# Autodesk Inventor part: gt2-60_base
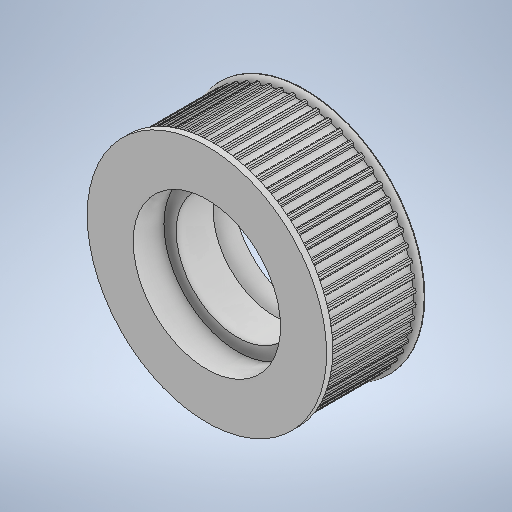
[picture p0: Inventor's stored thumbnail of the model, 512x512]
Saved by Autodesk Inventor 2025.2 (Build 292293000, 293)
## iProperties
Created: 2025-06
Part Number: gt2-60_base
Material: Generico
Document SubType Name: Modeling
Designer: Ryzen5700u
Density: 1 g/cm^3
Appearance: Default
Author: Ryzen5700u
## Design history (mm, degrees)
sketch "Schizzo1"
  geometry: C1 r 4.963 at (0, 0); A1 r 18.592 centre (0, 0) between (-0.5, -18.585) and (0.5, -18.585); A2 r 0.65 centre (0, -19) between (0.628, -18.833) and (0.5, -18.585); A3 r 0.2 centre (0.822, -18.782) between (0.628, -18.833) and (0.83, -18.982); A4 r 19 centre (0, 0) between (0.83, -18.982) and (1.158, -18.965); A5 r 0.2 centre (1.146, -18.765) between (1.158, -18.965) and (1.344, -18.796); A6 r 0.65 centre (1.986, -18.896) between (1.445, -18.536) and (1.344, -18.796); A7 r 18.592 centre (0, 0) between (1.445, -18.536) and (2.44, -18.431); A8 r 0.65 centre (1.986, -18.896) between (2.593, -18.664) and (2.44, -18.431); A9 r 0.2 centre (2.78, -18.593) between (2.593, -18.664) and (2.81, -18.791); A10 r 19 centre (0, 0) between (2.81, -18.791) and (3.134, -18.74); A11 r 0.2 centre (3.101, -18.542) between (3.134, -18.74) and (3.301, -18.552); A12 r 0.65 centre (3.95, -18.585) between (3.375, -18.283) and (3.301, -18.552); A13 r 18.592 centre (0, 0) between (3.375, -18.283) and (4.354, -18.075); A14 r 0.65 centre (3.95, -18.585) between (4.53, -18.291) and (4.354, -18.075); A15 r 0.2 centre (4.709, -18.201) between (4.53, -18.291) and (4.759, -18.394); A16 r 19 centre (0, 0) between (4.759, -18.394) and (5.076, -18.309); A17 r 0.2 centre (5.023, -18.117) between (5.076, -18.309) and (5.222, -18.106); A18 r 0.65 centre (5.871, -18.07) between (5.267, -17.83) and (5.222, -18.106); A19 r 18.592 centre (0, 0) between (5.267, -17.83) and (6.219, -17.521); A20 r 0.65 centre (5.871, -18.07) between (6.417, -17.717) and (6.219, -17.521); A21 r 0.2 centre (6.585, -17.609) between (6.417, -17.717) and (6.655, -17.796); A22 r 19 centre (0, 0) between (6.655, -17.796) and (6.962, -17.679); A23 r 0.2 centre (6.889, -17.492) between (6.962, -17.679) and (7.086, -17.461); A24 r 0.65 centre (7.728, -17.357) between (7.102, -17.182) and (7.086, -17.461); A25 r 18.592 centre (0, 0) between (7.102, -17.182) and (8.017, -16.775); A26 r 0.65 centre (7.728, -17.357) between (8.234, -16.95) and (8.017, -16.775); A27 r 0.2 centre (8.39, -16.824) between (8.234, -16.95) and (8.479, -17.003); A28 r 19 centre (0, 0) between (8.479, -17.003) and (8.772, -16.854); A29 r 0.2 centre (8.68, -16.677) between (8.772, -16.854) and (8.873, -16.624); A30 r 0.65 centre (9.5, -16.454) between (8.859, -16.346) and (8.873, -16.624); A31 r 18.592 centre (0, 0) between (8.859, -16.346) and (9.726, -15.845); A32 r 0.65 centre (9.5, -16.454) between (9.961, -15.996) and (9.726, -15.845); A33 r 0.2 centre (10.103, -15.855) between (9.961, -15.996) and (10.21, -16.024); A34 r 19 centre (0, 0) between (10.21, -16.024) and (10.486, -15.845); A35 r 0.2 centre (10.375, -15.678) between (10.486, -15.845) and (10.562, -15.606); A36 r 0.65 centre (11.168, -15.371) between (10.519, -15.33) and (10.562, -15.606); A37 r 18.592 centre (0, 0) between (10.519, -15.33) and (11.329, -14.742); A38 r 0.65 centre (11.168, -15.371) between (11.578, -14.867) and (11.329, -14.742); A39 r 0.2 centre (11.704, -14.712) between (11.578, -14.867) and (11.829, -14.869); A40 r 19 centre (0, 0) between (11.829, -14.869) and (12.084, -14.662); A41 r 0.2 centre (11.957, -14.508) between (12.084, -14.662) and (12.135, -14.416); A42 r 0.65 centre (12.713, -14.12) between (12.064, -14.146) and (12.135, -14.416); A43 r 18.592 centre (0, 0) between (12.064, -14.146) and (12.808, -13.477); A44 r 0.65 centre (12.713, -14.12) between (13.069, -13.575) and (12.808, -13.477); A45 r 0.2 centre (13.178, -13.408) between (13.069, -13.575) and (13.318, -13.551); A46 r 19 centre (0, 0) between (13.318, -13.551) and (13.551, -13.318); A47 r 0.2 centre (13.408, -13.178) between (13.551, -13.318) and (13.575, -13.069); A48 r 0.65 centre (14.12, -12.713) between (13.477, -12.808) and (13.575, -13.069); A49 r 18.592 centre (0, 0) between (13.477, -12.808) and (14.146, -12.064); A50 r 0.65 centre (14.12, -12.713) between (14.416, -12.135) and (14.146, -12.064); A51 r 0.2 centre (14.508, -11.957) between (14.416, -12.135) and (14.662, -12.084); A52 r 19 centre (0, 0) between (14.662, -12.084) and (14.869, -11.829); A53 r 0.2 centre (14.712, -11.704) between (14.869, -11.829) and (14.867, -11.578); A54 r 0.65 centre (15.371, -11.168) between (14.742, -11.329) and (14.867, -11.578); A55 r 18.592 centre (0, 0) between (14.742, -11.329) and (15.33, -10.519); A56 r 0.65 centre (15.371, -11.168) between (15.606, -10.562) and (15.33, -10.519); A57 r 0.2 centre (15.678, -10.375) between (15.606, -10.562) and (15.845, -10.486); A58 r 19 centre (0, 0) between (15.845, -10.486) and (16.024, -10.21); A59 r 0.2 centre (15.855, -10.103) between (16.024, -10.21) and (15.996, -9.961); A60 r 0.65 centre (16.454, -9.5) between (15.845, -9.726) and (15.996, -9.961); A61 r 18.592 centre (0, 0) between (15.845, -9.726) and (16.346, -8.859); A62 r 0.65 centre (16.454, -9.5) between (16.624, -8.873) and (16.346, -8.859); A63 r 0.2 centre (16.677, -8.68) between (16.624, -8.873) and (16.854, -8.772); A64 r 19 centre (0, 0) between (16.854, -8.772) and (17.003, -8.479)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; 361 further points
  constraints: 720 point on circle, 361 centre point
extrude "Estrusione1" new body sketch "Schizzo1" stored distance "d0" = 14; taper "d1" = 0 deg
sketch "Schizzo2"
  geometry: C1 r 19.5 at (0, 0); 1 further point
  constraints: 1 centre point, 1 coincident
  dimensions: "d2" = 39 diameter of C1
extrude "Estrusione2" join sketch "Schizzo2" distance "d3" = 1; taper "d4" = 0 deg
sketch "Schizzo5"
  geometry: 1 further point
hole "Foro1" sketch "Schizzo5" at (0, 0) diameter "d14" = 5.5; stored, may be unused: countersink angle "d18" = 90 deg, drill point angle "d20" = 0 deg; dims "d15" = 6, "d16" = 10, "d17" = 5.7, "d19" = 50
fillet "Raccordo2" dims "d48" = 0.9
mirror "Speculare1"
sketch "Schizzo11"
  geometry: C1 r 19.5 at (0, 0) reference; 2 further points
  constraints: 1 coincident
hole "Foro4" sketch "Schizzo11" at (0, 0) diameter "d52" = 24; stored, may be unused: countersink angle "d56" = 90 deg, drill point angle "d58" = 118 deg; dims "d53" = 6, "d54" = 4, "d55" = 2, "d57" = 8
sketch "Schizzo12"
  geometry: C1 r 12 at (0, 0) reference; C2 r 10 at (0, 0); 1 further point
  constraints: 1 centre point, 1 coincident
  dimensions: "d59" = 20 diameter of C2
extrude "Estrusione8" join sketch "Schizzo12" stored distance "d60" = 6; taper "d61" = 0 deg
node "Solido1"
